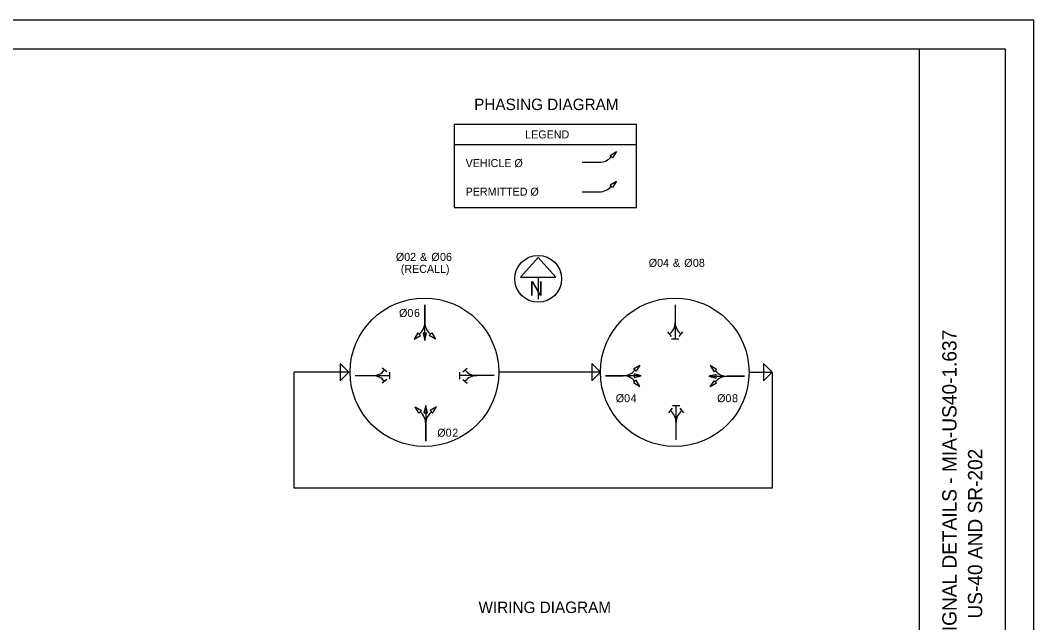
# Model space of a CAD drawing. Extents: x 0 to 680, y -24 to 440.
# Drawn here: x 325.4 to 680, y 229 to 440 of the extents above; entities that cross this region are included whole.
import ezdxf

# ---------------------------------------------------------------- set-up
doc = ezdxf.new("R2010")
doc.units = 0
for name, color, linetype in [('SH_Border', 7, 'Continuous'), ('SH_Cut_Line', 7, 'Continuous'), ('SH_Data', 7, 'Continuous'), ('SH_Masking', 7, 'Continuous'), ('SH_Text', 7, 'Continuous')]:
    doc.layers.add(name, color=color, linetype=linetype)

msp = doc.modelspace()

# ---------------------------------------------------------------- linework, layer by layer
at = {"layer": 'SH_Border'}
msp.add_line((640, 10), (640, 430), dxfattribs=at)
msp.add_lwpolyline([(30, 430), (670, 430), (670, 10), (30, 10)], close=True, dxfattribs=at)
at = {"layer": 'SH_Cut_Line'}
msp.add_lwpolyline([(0, 0), (680, 0), (680, 440), (0, 440)], close=True, dxfattribs=at)
at = {"layer": 'SH_Data'}
for p, q in [((477.29, 396.53), (541.06, 396.53)), ((521.97, 390.26), (528.08, 390.27)), ((521.97, 379.93), (528.08, 379.93)), ((466.97, 327.88), (466.97, 340.34)), ((466.97, 340.34), (466.97, 334.23)), ((466.97, 327.88), (466.97, 340.34)), ((466.97, 340.34), (466.97, 334.23)), ((554.56, 340.34), (554.56, 328.33)), ((554.56, 340.34), (554.56, 328.33)), ((554.56, 340.34), (554.56, 334.23)), ((554.56, 340.34), (554.56, 334.23)), ((553.22, 329.3), (551.94, 330.9)), ((555.9, 329.3), (557.18, 330.9)), ((555.83, 328.33), (553.29, 328.33)), ((555.83, 328.33), (553.29, 328.33)), ((440.42, 316.76), (421.21, 316.76)), ((421.21, 276.15), (421.21, 316.76)), ((453.65, 316.91), (452.06, 318.19)), ((454.63, 316.84), (454.63, 314.3)), ((479.24, 314.3), (479.24, 316.84)), ((480.21, 316.91), (481.81, 318.19)), ((528.42, 316.76), (492.82, 316.76)), ((580.4, 316.76), (588.53, 316.76)), ((588.53, 316.76), (588.53, 276.14)), ((442.61, 315.57), (454.63, 315.57)), ((442.61, 315.57), (448.72, 315.57)), ((442.61, 315.57), (448.72, 315.57)), ((453.65, 314.23), (452.06, 312.95)), ((491.25, 315.57), (479.24, 315.57)), ((480.21, 314.23), (481.81, 312.95)), ((491.25, 315.57), (485.14, 315.57)), ((491.25, 315.57), (485.14, 315.57)), ((530.2, 315.54), (536.31, 315.54)), ((542.66, 315.54), (530.2, 315.54)), ((530.2, 315.54), (536.31, 315.54)), ((566.37, 315.33), (578.83, 315.33)), ((566.37, 315.33), (578.83, 315.33)), ((578.83, 315.33), (572.72, 315.33)), ((578.83, 315.33), (572.72, 315.33)), ((467.29, 305.09), (467.29, 292.63)), ((553.61, 305.09), (556.14, 305.09)), ((554.88, 293.08), (554.88, 305.09)), ((553.54, 304.12), (552.26, 302.52)), ((556.21, 304.12), (557.49, 302.52)), ((467.29, 292.63), (467.29, 298.74)), ((467.29, 292.63), (467.29, 298.74)), ((554.88, 293.08), (554.88, 299.19)), ((554.88, 293.08), (554.88, 299.19)), ((588.53, 276.14), (421.21, 276.15))]:
    msp.add_line(p, q, dxfattribs=at)
for points in [[(541.06, 403.53), (477.29, 403.53), (477.29, 374.44), (541.06, 374.44)], [(531.77, 392.69), (533.98, 394.01), (532.65, 391.8)], [(531.77, 382.35), (533.98, 383.67), (532.65, 381.46)], [(464.55, 330.54), (463.22, 328.33), (465.43, 329.66)], [(466.35, 330.38), (466.97, 327.88), (467.6, 330.38)], [(466.35, 330.38), (466.97, 327.88), (467.6, 330.38)], [(469.39, 330.54), (470.72, 328.33), (468.51, 329.66)], [(440.42, 316.76), (437.39, 319.79), (437.38, 313.73)], [(528.42, 316.76), (525.39, 319.79), (525.39, 313.73)], [(540, 317.97), (542.21, 319.29), (540.88, 317.08)], [(588.53, 316.76), (585.5, 319.79), (585.49, 313.73)], [(540.16, 314.92), (542.66, 315.54), (540.16, 316.17)], [(568.87, 315.96), (566.37, 315.33), (568.87, 314.71)], [(568.87, 315.96), (566.37, 315.33), (568.87, 314.71)], [(569.03, 317.76), (566.81, 319.08), (568.14, 316.87)], [(540, 313.12), (542.21, 311.8), (540.88, 314.01)], [(569.03, 312.91), (566.81, 311.59), (568.14, 313.79)], [(467.91, 302.59), (467.29, 305.09), (466.66, 302.59)], [(464.87, 302.43), (463.54, 304.65), (465.75, 303.32)], [(469.71, 302.43), (471.04, 304.64), (468.83, 303.32)]]:
    msp.add_lwpolyline(points, close=True, dxfattribs=at)
for centre in [(466.83, 316.76), (554.41, 316.76)]:
    msp.add_circle(centre, 25.99, dxfattribs=at)
for centre, start, end in [((528.08, 395.57), 270.0129, 321.2136), ((528.08, 385.23), 270, 321.2007), ((461.67, 334.23), 308.7864, 359.9871), ((472.27, 334.23), 180, 231.2007), ((549.26, 334.23), 308.7993, 0), ((559.86, 334.23), 180, 231.2007), ((448.72, 320.87), 270, 321.2007), ((485.14, 320.87), 218.7993, 270), ((536.31, 320.85), 270, 321.2007), ((572.72, 320.63), 218.7864, 269.9871), ((448.72, 310.27), 38.7993, 90), ((485.14, 310.27), 90, 141.2007), ((536.31, 310.24), 38.7864, 89.9871), ((572.72, 310.03), 90, 141.2007), ((461.99, 298.74), 360, 51.2007), ((472.59, 298.74), 128.7864, 179.9871), ((549.57, 299.19), 360, 51.2007), ((560.18, 299.19), 128.7993, 180)]:
    msp.add_arc(centre, 5.3, start, end, dxfattribs=at)
at = {"layer": 'SH_Masking'}
msp.add_circle((506.6, 349.45), 8.2, dxfattribs=at)
at = {"layer": 'SH_Text'}
for p, q in [((506.6, 356.92), (500.45, 350.1)), ((512.76, 350.1), (506.6, 356.92)), ((500.45, 350.1), (512.76, 350.1)), ((506.6, 350.1), (506.6, 342.36))]:
    msp.add_line(p, q, dxfattribs=at)
msp.add_circle((506.6, 349.45), 8.2, dxfattribs=at)

# ---------------------------------------------------------------- texts
at = {"layer": 'SH_Data'}
for s, p in [('TRAFFIC SIGNAL DETAILS - MIA-US40-1.637', (653, 191.54)), ('US-40 AND SR-202', (662, 230.52))]:
    msp.add_text(s, height=5, rotation=90, dxfattribs=at).set_placement(p)
at = {"layer": 'SH_Text'}
for s, height, p in [('PHASING DIAGRAM', 4, (484.23, 408.55)), ('LEGEND', 2.8, (502.09, 398.63)), ('VEHICLE Ø', 2.8, (481.25, 388.59)), ('PERMITTED Ø', 2.8, (481.25, 378.59)), ('Ø02', 2.8, (456.85, 355.75)), (' & ', 2.8, (464.24, 355.75)), ('Ø', 2.8, (469.25, 355.75)), ('06', 2.8, (472.29, 355.75)), ('Ø04', 2.8, (545.32, 353.65)), (' & ', 2.8, (552.72, 353.65)), ('Ø', 2.8, (557.72, 353.65)), ('08', 2.8, (560.76, 353.65)), ('(RECALL)', 2.8, (458.55, 351.55)), ('Ø0', 2.8, (457.95, 336.11)), ('6', 2.8, (463.17, 336.11)), ('Ø0', 2.8, (533.77, 306.27)), ('4', 2.8, (538.99, 306.27)), ('Ø0', 2.8, (569.23, 306.27)), ('8', 2.8, (574.45, 306.27)), ('Ø0', 2.8, (471.34, 294.19)), ('2', 2.8, (476.55, 294.19)), ('WIRING DIAGRAM', 4, (485.76, 232.45))]:
    msp.add_text(s, height=height, dxfattribs=at).set_placement(p)
msp.add_text('N', height=5, rotation=360, dxfattribs=at).set_placement((503.58, 343.62))

doc.saveas('drawing.dxf')
